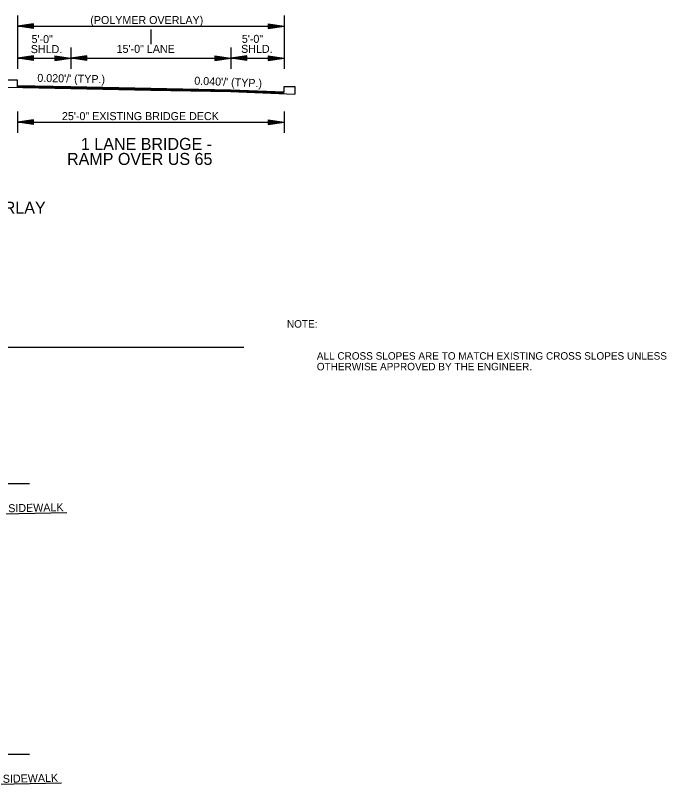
# Model space of a CAD drawing. Extents: x 550980 to 1930787, y -1972975 to 596640.
# Drawn here: x 551840 to 552450, y -1966549 to -1965822 of the extents above; entities that cross this region are included whole.
import ezdxf

# ---------------------------------------------------------------- set-up
doc = ezdxf.new("R2010")
doc.units = 0
doc.layers.add('R_Border', color=7, linetype='Continuous')
doc.layers.add('R_Border Notes', color=7, linetype='Continuous')

msp = doc.modelspace()

# ---------------------------------------------------------------- linework, layer by layer
at = {"layer": 'R_Border'}
for p, q in [((551842.14, -1965822.21), (551842.14, -1965872.21)), ((552092.13, -1965822.22), (552092.13, -1965872.22)), ((551857.14, -1965829.96), (551842.14, -1965832.21)), ((551857.14, -1965830.34), (551844.64, -1965832.21)), ((551857.14, -1965830.72), (551847.22, -1965832.21)), ((551857.14, -1965831.1), (551849.72, -1965832.21)), ((551857.14, -1965831.48), (551852.26, -1965832.21)), ((551857.14, -1965831.86), (551854.77, -1965832.21)), ((551857.14, -1965834.46), (551857.14, -1965829.96)), ((552077.13, -1965829.97), (552092.13, -1965832.22)), ((552077.13, -1965829.97), (552077.13, -1965834.47)), ((552077.13, -1965830.35), (552089.63, -1965832.22)), ((552077.13, -1965830.73), (552087.05, -1965832.22)), ((552077.13, -1965831.1), (552084.55, -1965832.22)), ((552077.13, -1965831.49), (552082.01, -1965832.22)), ((552077.13, -1965831.87), (552079.5, -1965832.22)), ((551842.14, -1965832.21), (552092.14, -1965832.21)), ((551857.14, -1965834.46), (551842.14, -1965832.21)), ((551857.14, -1965834.09), (551844.64, -1965832.21)), ((551857.14, -1965833.71), (551847.22, -1965832.21)), ((551857.14, -1965833.33), (551849.72, -1965832.21)), ((551857.14, -1965832.94), (551852.26, -1965832.21)), ((551857.14, -1965832.57), (551854.77, -1965832.21)), ((551967.14, -1965835.21), (551967.14, -1965849.21)), ((552077.13, -1965834.47), (552092.13, -1965832.22)), ((552077.13, -1965832.96), (552082.01, -1965832.22)), ((552077.13, -1965833.71), (552087.05, -1965832.22)), ((552077.13, -1965834.1), (552089.63, -1965832.22)), ((552077.13, -1965833.34), (552084.55, -1965832.22)), ((552077.13, -1965832.57), (552079.5, -1965832.22)), ((551892.14, -1965852.21), (551892.14, -1965872.21)), ((552042.14, -1965852.21), (552042.14, -1965872.21)), ((551857.14, -1965859.96), (551842.14, -1965862.21)), ((551857.14, -1965860.34), (551844.64, -1965862.21)), ((551857.14, -1965860.72), (551847.22, -1965862.21)), ((551857.14, -1965864.46), (551857.14, -1965859.96)), ((551877.14, -1965859.96), (551892.14, -1965862.21)), ((551877.14, -1965859.96), (551877.14, -1965864.46)), ((551877.14, -1965860.34), (551889.63, -1965862.21)), ((551877.14, -1965860.72), (551887.05, -1965862.21)), ((551907.14, -1965859.96), (551892.14, -1965862.21)), ((551907.14, -1965860.34), (551894.64, -1965862.21)), ((551907.14, -1965860.72), (551897.22, -1965862.21)), ((551907.14, -1965864.46), (551907.14, -1965859.96)), ((552027.14, -1965859.96), (552042.14, -1965862.21)), ((552027.14, -1965859.96), (552027.14, -1965864.46)), ((552027.14, -1965860.34), (552039.63, -1965862.21)), ((552027.14, -1965860.72), (552037.05, -1965862.21)), ((552057.14, -1965859.96), (552042.14, -1965862.21)), ((552057.14, -1965860.34), (552044.64, -1965862.21)), ((552057.14, -1965860.72), (552047.22, -1965862.21)), ((552057.14, -1965864.46), (552057.14, -1965859.96)), ((552077.13, -1965859.97), (552092.13, -1965862.22)), ((552077.13, -1965859.97), (552077.13, -1965864.47)), ((552077.13, -1965860.35), (552089.63, -1965862.22)), ((552077.13, -1965860.73), (552087.05, -1965862.22)), ((551842.14, -1965862.21), (552092.14, -1965862.21)), ((551857.14, -1965864.46), (551842.14, -1965862.21)), ((551857.14, -1965864.09), (551844.64, -1965862.21)), ((551857.14, -1965863.71), (551847.22, -1965862.21)), ((551857.14, -1965861.1), (551849.72, -1965862.21)), ((551857.14, -1965863.33), (551849.72, -1965862.21)), ((551857.14, -1965861.48), (551852.26, -1965862.21)), ((551857.14, -1965862.94), (551852.26, -1965862.21)), ((551857.14, -1965861.86), (551854.77, -1965862.21)), ((551857.14, -1965862.57), (551854.77, -1965862.21)), ((551877.14, -1965861.1), (551884.56, -1965862.21)), ((551877.14, -1965861.49), (551882.01, -1965862.21)), ((551877.14, -1965861.86), (551879.51, -1965862.21)), ((551877.14, -1965864.46), (551892.14, -1965862.21)), ((551877.14, -1965862.95), (551882.01, -1965862.21)), ((551877.14, -1965863.71), (551887.05, -1965862.21)), ((551877.14, -1965864.09), (551889.63, -1965862.21)), ((551877.14, -1965863.33), (551884.56, -1965862.21)), ((551877.14, -1965862.57), (551879.51, -1965862.21)), ((551907.14, -1965864.46), (551892.14, -1965862.21)), ((551907.14, -1965864.09), (551894.64, -1965862.21)), ((551907.14, -1965863.71), (551897.22, -1965862.21)), ((551907.14, -1965861.1), (551899.72, -1965862.21)), ((551907.14, -1965863.33), (551899.72, -1965862.21)), ((551907.14, -1965861.48), (551902.26, -1965862.21)), ((551907.14, -1965862.94), (551902.26, -1965862.21)), ((551907.14, -1965861.86), (551904.77, -1965862.21)), ((551907.14, -1965862.57), (551904.77, -1965862.21)), ((552027.14, -1965861.1), (552034.56, -1965862.21)), ((552027.14, -1965861.49), (552032.01, -1965862.21)), ((552027.14, -1965861.86), (552029.51, -1965862.21)), ((552027.14, -1965864.46), (552042.14, -1965862.21)), ((552027.14, -1965862.95), (552032.01, -1965862.21)), ((552027.14, -1965863.71), (552037.05, -1965862.21)), ((552027.14, -1965864.09), (552039.63, -1965862.21)), ((552027.14, -1965863.33), (552034.56, -1965862.21)), ((552027.14, -1965862.57), (552029.51, -1965862.21)), ((552057.14, -1965864.46), (552042.14, -1965862.21)), ((552057.14, -1965864.09), (552044.64, -1965862.21)), ((552057.14, -1965863.71), (552047.22, -1965862.21)), ((552057.14, -1965861.1), (552049.72, -1965862.21)), ((552057.14, -1965863.33), (552049.72, -1965862.21)), ((552057.14, -1965861.48), (552052.26, -1965862.21)), ((552057.14, -1965862.94), (552052.26, -1965862.21)), ((552057.14, -1965861.86), (552054.77, -1965862.21)), ((552057.14, -1965862.57), (552054.77, -1965862.21)), ((552077.13, -1965861.1), (552084.55, -1965862.22)), ((552077.13, -1965861.49), (552082.01, -1965862.22)), ((552077.13, -1965861.87), (552079.5, -1965862.22)), ((552077.13, -1965864.47), (552092.13, -1965862.22)), ((552077.13, -1965862.96), (552082.01, -1965862.22)), ((552077.13, -1965863.71), (552087.05, -1965862.22)), ((552077.13, -1965864.1), (552089.63, -1965862.22)), ((552077.13, -1965863.34), (552084.55, -1965862.22)), ((552077.13, -1965862.57), (552079.5, -1965862.22)), ((551842.14, -1965912.21), (551842.14, -1965932.21)), ((552092.14, -1965912.21), (552092.14, -1965932.21)), ((551857.14, -1965919.96), (551842.14, -1965922.21)), ((551842.14, -1965922.21), (552092.14, -1965922.21)), ((551857.14, -1965924.46), (551842.14, -1965922.21)), ((551857.14, -1965920.34), (551844.64, -1965922.21)), ((551857.14, -1965924.09), (551844.64, -1965922.21)), ((551857.14, -1965920.72), (551847.22, -1965922.21)), ((551857.14, -1965923.71), (551847.22, -1965922.21)), ((551857.14, -1965921.1), (551849.72, -1965922.21)), ((551857.14, -1965923.33), (551849.72, -1965922.21)), ((551857.14, -1965921.48), (551852.26, -1965922.21)), ((551857.14, -1965922.94), (551852.26, -1965922.21)), ((551857.14, -1965921.86), (551854.77, -1965922.21)), ((551857.14, -1965922.57), (551854.77, -1965922.21)), ((551857.14, -1965924.46), (551857.14, -1965919.96)), ((552077.14, -1965919.96), (552092.14, -1965922.21)), ((552077.14, -1965919.96), (552077.14, -1965924.46)), ((552077.14, -1965920.34), (552089.63, -1965922.21)), ((552077.14, -1965920.72), (552087.05, -1965922.21)), ((552077.14, -1965921.1), (552084.56, -1965922.21)), ((552077.14, -1965921.49), (552082.01, -1965922.21)), ((552077.14, -1965921.86), (552079.51, -1965922.21)), ((552077.14, -1965924.46), (552092.14, -1965922.21)), ((552077.14, -1965922.95), (552082.01, -1965922.21)), ((552077.14, -1965923.71), (552087.05, -1965922.21)), ((552077.14, -1965924.09), (552089.63, -1965922.21)), ((552077.14, -1965923.33), (552084.56, -1965922.21)), ((552077.14, -1965922.57), (552079.51, -1965922.21)), ((550992.91, -1966132.85), (552054.18, -1966132.85)), ((551273.18, -1966260.82), (551853.18, -1966260.82)), ((551828.28, -1966289.13), (551888.28, -1966287.93)), ((551273.18, -1966514.25), (551853.18, -1966514.25))]:
    msp.add_line(p, q, dxfattribs=at)
for points in [[(551842.14, -1965889.21), (551842.14, -1965882.71), (551832.14, -1965882.71), (551832.14, -1965889.31)], [(551832.14, -1965889.31), (551892.14, -1965890.51), (551967.14, -1965892.01), (552042.14, -1965893.51), (552102.13, -1965895.91)], [(551842.14, -1965887.71), (551892.14, -1965888.71), (551967.14, -1965890.21), (552042.14, -1965891.71), (552092.13, -1965893.71)], [(551842.14, -1965888.01), (551892.14, -1965889.01), (551967.14, -1965890.51), (552042.14, -1965892.01), (552092.13, -1965894.01)], [(551842.14, -1965888.31), (551892.14, -1965889.31), (551967.14, -1965890.81), (552042.14, -1965892.31), (552092.13, -1965894.31)], [(551842.14, -1965888.61), (551892.14, -1965889.61), (551967.14, -1965891.11), (552042.14, -1965892.61), (552092.13, -1965894.61)], [(551842.14, -1965888.91), (551892.14, -1965889.91), (551967.14, -1965891.41), (552042.14, -1965892.91), (552092.13, -1965894.91)], [(551842.14, -1965889.21), (551892.14, -1965890.21), (551967.14, -1965891.71), (552042.14, -1965893.21), (552092.13, -1965895.21)], [(552092.13, -1965893.71), (552092.13, -1965888.71), (552102.13, -1965888.71), (552102.13, -1965895.91)], [(551823.18, -1966549.25), (551823.18, -1966542.45), (551883.18, -1966541.25), (551883.18, -1966541.25)]]:
    msp.add_lwpolyline(points, dxfattribs=at)

# ---------------------------------------------------------------- texts
for s, height, p in [(' (POLYMER OVERLAY)', 7.5, (551907.46, -1965830.21)), ('5\'-0" ', 7.5, (551855.18, -1965848.05)), ('5\'-0" ', 7.5, (552052.33, -1965847.82)), ('SHLD.', 7.5, (551854.5, -1965857.44)), ('15\'-0" LANE', 7.5, (551934.95, -1965857.21)), ('SHLD.', 7.5, (552051.65, -1965857.21)), ('25\'-0" EXISTING BRIDGE DECK', 7.5, (551883.69, -1965920.21)), ('1 LANE BRIDGE -', 11.25, (551901.5, -1965948.13)), ('RAMP OVER US 65', 11.25, (551888.48, -1965962.21)), ('25 FT. CLEAR ROADWAY BRIDGE - POLYMER OVERLAY', 11.25, (551464.66, -1966007.84))]:
    msp.add_text(s, height=height, dxfattribs=at).set_placement(p)
for s, rotation, p in [("0.020'/' (TYP.)", 358.8542, (551860.56, -1965884.36)), ("0.040'/' (TYP.)", 357.7084, (552007.65, -1965886.95)), ('SIDEWALK', 1.1458, (551833.42, -1966287.66)), ('SIDEWALK', 1.1458, (551828.32, -1966541.16))]:
    msp.add_text(s, height=7.5, rotation=rotation, dxfattribs=at).set_placement(p)
at = {"layer": 'R_Border Notes'}
for s, p in [('NOTE: ', (552094.62, -1966114.65)), ('ALL CROSS SLOPES ARE TO MATCH EXISTING CROSS SLOPES UNLESS ', (552122.62, -1966144.65)), ('OTHERWISE APPROVED BY THE ENGINEER.', (552122.62, -1966154.65))]:
    msp.add_text(s, height=7, dxfattribs=at).set_placement(p)

doc.saveas('drawing.dxf')
